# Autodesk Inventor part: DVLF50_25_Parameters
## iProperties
Created: 2010-03
Part Number: DVLF50_25_Parameters
Document SubType Name: Modeling
Designer: TB
Density: 1 g/cm^3
Slaglengde: 100.000 mm
Vinkel_Plussport: 0.00 deg
Vinkel_Minusport: 0.00 deg
Forlengelse_rør: 0.000 mm
Author: TB
